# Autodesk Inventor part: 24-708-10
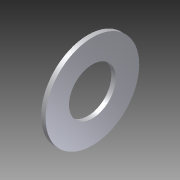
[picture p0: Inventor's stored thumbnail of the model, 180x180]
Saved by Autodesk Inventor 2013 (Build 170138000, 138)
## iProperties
Created: 2004-11
Part Number: 24-708-10
Document SubType Name: Modeling
Designer: Autodesk, Inc.
Manufacturer: Standard
Standards Organization: Custom
Description: WASHER, SPRING, PARKER IPS, M10
Catalog Web Link: http://www.parker.com/ead/cm1.asp?cmid=809
Vendor: PARKER IPS
Mass: 0.25977 g
Surface Area: 6.18501 cm^2
Volume: 0.25977 cm^3
Density: 1 g/cm^3
Material: Allgemein
CAGE: 1LJX3
Dept. ID: Product Design
Description #2: ---
Finish #1: ---
Finish #2: ---
Material ID: ---
Project Number: ---
Description: Washers
Order Number: 24-708-10
Selection: Spring Washer M10
Supplier: Parker Hannifin Corp., Industrial Profile Systems Div.
Author: Autodesk, Inc.
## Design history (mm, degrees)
feature "Base1"
body "Solid1"
